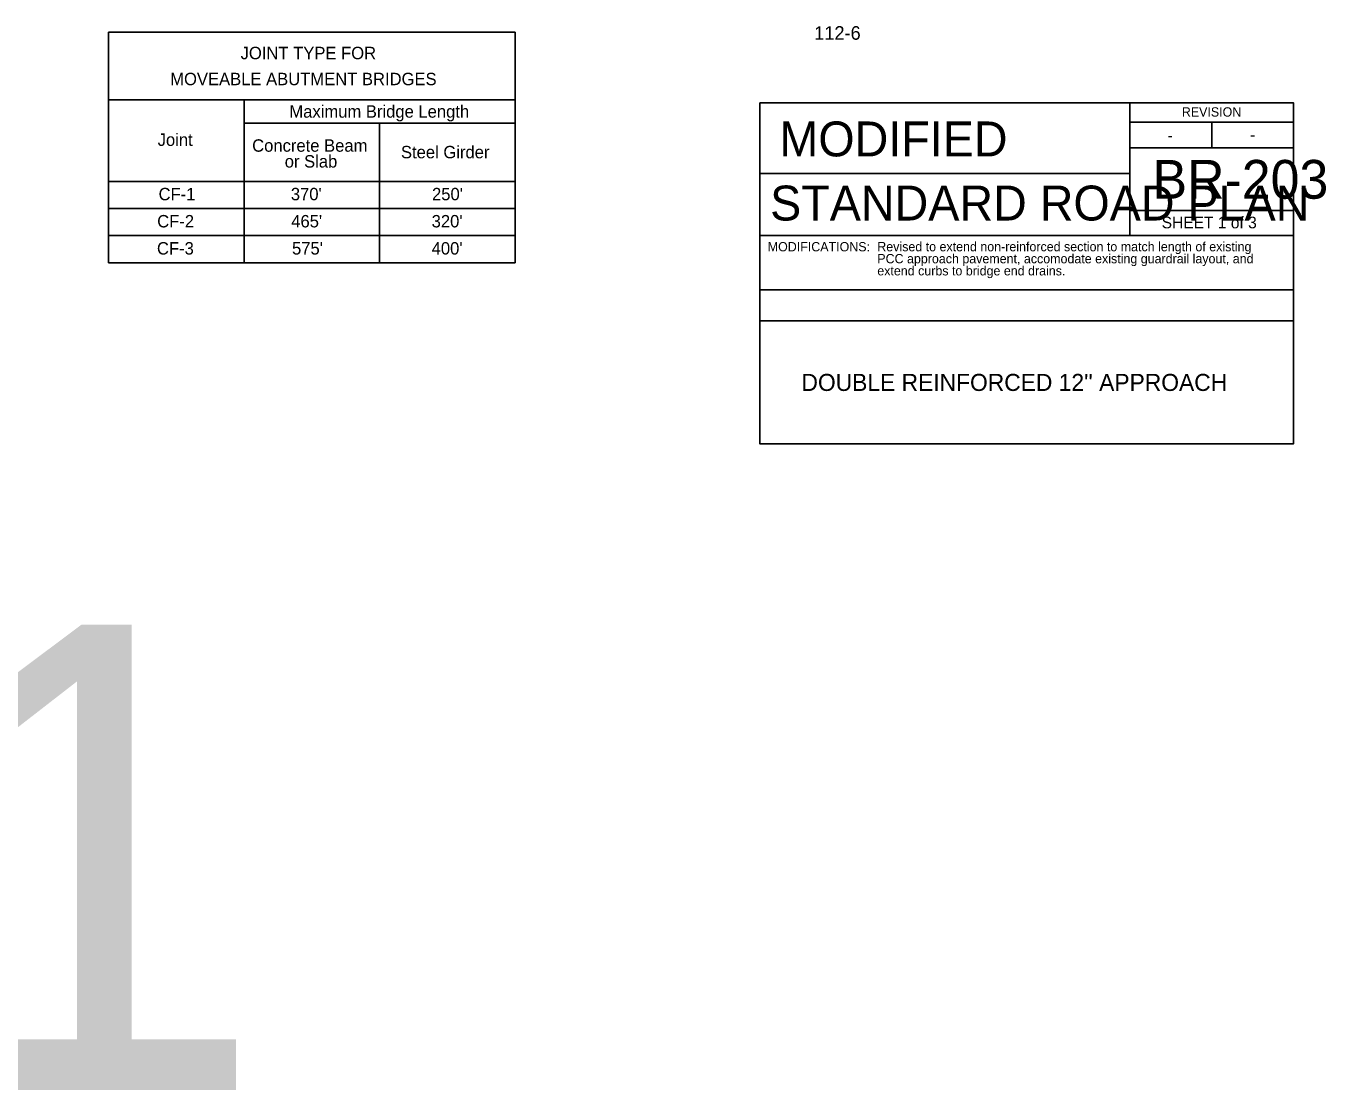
# Model space of a CAD drawing. Extents: x 5546 to 81668, y 3174 to 15999.
# Drawn here: x 11633 to 13310, y 10409 to 11781 of the extents above; entities that cross this region are included whole.
import ezdxf

# ---------------------------------------------------------------- set-up
doc = ezdxf.new("R2010")
doc.units = 0
for name, color, linetype in [('PS_BOLT', 7, 'Continuous'), ('PS_HIDDEN', 7, 'Continuous'), ('SheetAddenda', 7, 'Continuous'), ('tdCoLegendTitle', 7, 'Continuous'), ('tdCoShieldCoRte', 7, 'Continuous'), ('tdCoShieldUsRte', 7, 'Continuous')]:
    doc.layers.add(name, color=color, linetype=linetype)

msp = doc.modelspace()

# ---------------------------------------------------------------- linework, layer by layer
at = {"layer": 'PS_HIDDEN'}
for p, q in [((11739, 11773.5), (12263.9, 11773.5)), ((11739, 11773.5), (11739, 11476)), ((12263.9, 11773.5), (12263.9, 11476)), ((11739, 11686), (12263.9, 11686)), ((11914, 11686), (11914, 11476)), ((11914, 11656), (12263.9, 11656)), ((12088.9, 11656), (12088.9, 11476)), ((11739, 11581), (12263.9, 11581)), ((11739, 11546), (12263.9, 11546)), ((11739, 11511), (12263.9, 11511)), ((11739, 11476), (12263.9, 11476))]:
    msp.add_line(p, q, dxfattribs=at)
at = {"layer": 'tdCoLegendTitle'}
for p, q in [((13056.6, 11682.4), (13056.6, 11591)), ((13056.6, 11657.5), (13267.5, 11657.5)), ((13162.1, 11657.5), (13162.1, 11624.2)), ((13056.6, 11624.2), (13267.5, 11624.2)), ((12579.5, 11591), (13056.6, 11591)), ((13056.6, 11591), (13056.6, 11511)), ((13267.5, 11543.2), (13056.6, 11543.2)), ((12579.5, 11511), (13267.5, 11511)), ((12579.5, 11441), (13267.5, 11441)), ((12579.5, 11401), (13267.5, 11401)), ((12579.5, 11401), (13267.5, 11401))]:
    msp.add_line(p, q, dxfattribs=at)
msp.add_lwpolyline([(12579.5, 11682.4), (13267.5, 11682.4), (13267.5, 11242.4), (12579.5, 11242.4)], close=True, dxfattribs=at)

# ---------------------------------------------------------------- texts
at = {"layer": 'PS_BOLT'}
for s, p in [('JOINT TYPE FOR', (11909.6, 11738.5)), ('MOVEABLE ABUTMENT BRIDGES', (11818.8, 11705))]:
    msp.add_text(s, height=16, dxfattribs=at).set_placement(p)
at = {"layer": 'PS_HIDDEN'}
for s, p in [('Maximum Bridge Length', (11972.5, 11663.1)), ('Joint', (11802.6, 11626.7)), ('Concrete Beam', (11924.5, 11619.2)), ('Steel Girder', (12116.4, 11610.7)), ('or Slab', (11966.5, 11598.8)), ('CF-1', (11803.8, 11556.6)), ("370' ", (11974.4, 11556.6)), ("250'", (12156.5, 11556.6)), ('CF-2', (11802, 11521.6)), ("465'", (11974.9, 11521.6)), ("320'", (12156, 11521.6)), ('CF-3', (11801.7, 11486.6)), ("400'", (12156, 11486.6)), ("575'", (11975.9, 11486.6))]:
    msp.add_text(s, height=16, dxfattribs=at).set_placement(p)
at = {"layer": 'SheetAddenda'}
msp.add_text('112-6', height=17.5, dxfattribs=at).set_placement((12649.5, 11763.6))
msp.add_text('112-6', height=17.5, dxfattribs=at).set_placement((12649.5, 11763.6))
at = {"layer": 'tdCoLegendTitle'}
for s, height, p in [('REVISION', 12, (13123.6, 11664.5)), ('-', 15, (13105.1, 11633)), ('-', 15, (13211.6, 11633.5)), ('BR-203', 50, (13085.8, 11558.6)), ('STANDARD ROAD PLAN', 45.001, (12592.6, 11530.5)), ('SHEET 1 of 3', 15, (13097.6, 11520.4)), ('Revised to extend non-reinforced section to match length of existing ', 12, (12730.8, 11490.8)), ('PCC approach pavement, accomodate existing guardrail layout, and ', 12, (12730.8, 11475.3)), ('extend curbs to bridge end drains.', 12, (12730.8, 11459.7)), ("DOUBLE REINFORCED 12'' APPROACH", 22, (12633, 11310.7))]:
    msp.add_text(s, height=height, dxfattribs=at).set_placement(p)
at = {"layer": 'tdCoShieldCoRte'}
msp.add_text('1', height=600, dxfattribs=at).set_placement((11496.6, 10409.2))
at = {"layer": 'tdCoShieldUsRte'}
for s, height, p in [('MODIFIED', 45, (12604.6, 11613.2)), ('MODIFICATIONS:', 12, (12589.5, 11490.7))]:
    msp.add_text(s, height=height, dxfattribs=at).set_placement(p)

doc.saveas('drawing.dxf')
